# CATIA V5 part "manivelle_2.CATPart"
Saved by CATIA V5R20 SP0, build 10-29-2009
Part number: manivelle_2
Bounding box of the stored display mesh (mm): x -10 to 0, y -170 to -90, z 40 to 60
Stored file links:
  D:\Dropbox\IAO_2011\MMS_GR2\IAO_2011_1491_mcabanel\IAO_2011_1491_mcabanel\manivelle_2.CATPart
  U:\2A\IAO\Projet\ass\kin\IAO_mcabanel.CATProduct
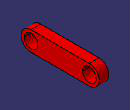
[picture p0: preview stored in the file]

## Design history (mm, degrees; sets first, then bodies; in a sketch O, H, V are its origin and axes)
Set1
  Plane1: linked copy from another document
  Line1: linked copy from another document
  Point1: linked copy from another document
  Point2: linked copy from another document
Body1 (main body)
  Sketch1 on Plane1, origin (-10, 0, 0), H (0, 1, 0), V (0, 0, 1)
    construction line L1 (-160, 50) -> (-100, 50)
    point P1 (-160, 50)
    point P2 (-100, 50)
    line L2 (-160, 60) -> (-100, 60)
    line L3 (-100, 40) -> (-160, 40)
    arc A1 centre (-100, 50) radius 10 from (-100, 60) to (-100, 40) cw
    arc A2 centre (-160, 50) radius 10 from (-160, 40) to (-160, 60) cw
    reference projected line E1 (-100, 50) -> (-160, 50) from Line1
    reference projected point E2 (-100, 50) from Point1
    circle A3 centre (-160, 50) radius 7
    point P7 (-160, 50)
    circle A4 centre (-100, 50) radius 7
    point P8 (-100, 50)
    reference projected point E3 (-100, 50) from Point1
    reference projected point E4 (-160, 50) from Point2
    reference projected point E5 (-160, 50) from Point2
    distance L1 L2 = 10
    radius A4 = 7
    radius A3 = 7
    tangency: A1 L2, A2 L2, A1 L3, A2 L3
    coincidence: P1 E1, P2 E2, P8 E3, E4 P7, P1 E5
  Pad1: profile Sketch1, direction (1, 0, 0), length 10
